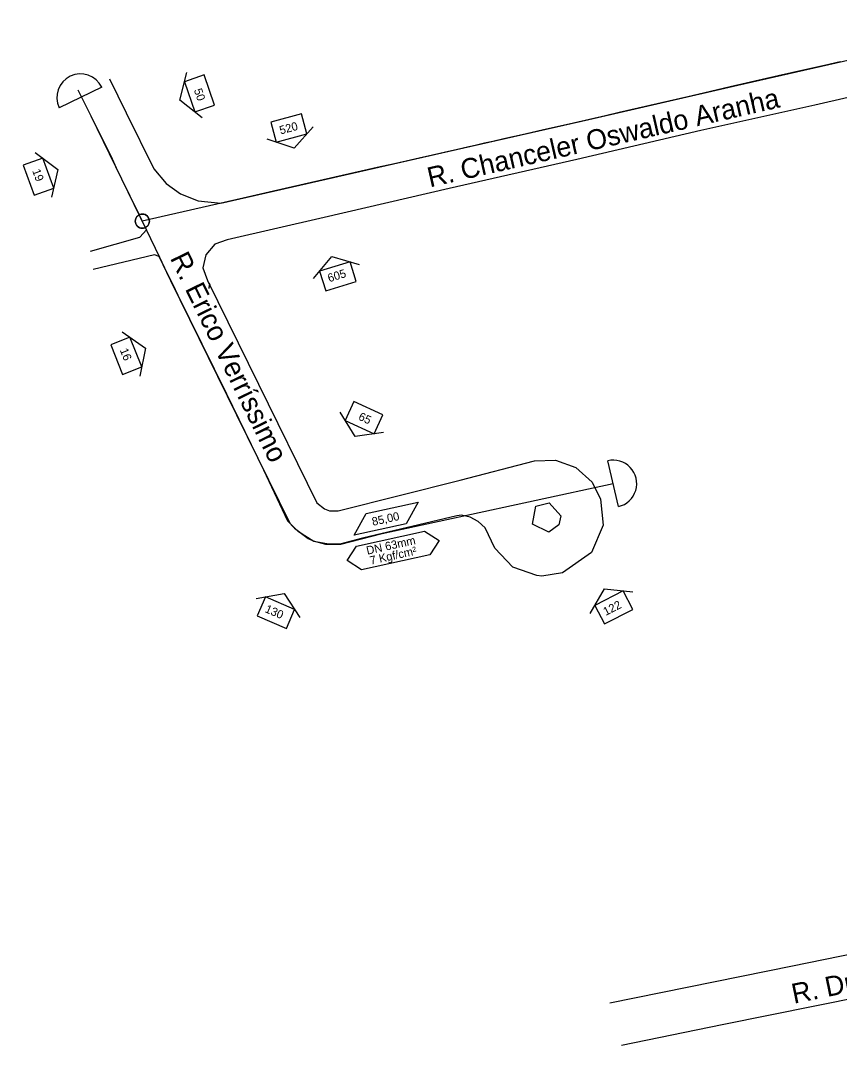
# Model space of a CAD drawing. Extents: x 656692 to 673945, y 7585994 to 7599066.
# Drawn here: x 669246.9 to 669542.8, y 7591875.8 to 7592245.9 of the extents above; entities that cross this region are included whole.
import ezdxf

# ---------------------------------------------------------------- set-up
doc = ezdxf.new("R2010")
doc.units = 0
for name, color, linetype in [('FORMATO', 7, 'Continuous'), ('LOGRADOURO', 7, 'Continuous'), ('LOGRADOURO_TEXTO', 7, 'Continuous'), ('NUM_REF', 7, 'Continuous'), ('SIMBOLO', 7, 'Continuous'), ('TEXTO', 7, 'Continuous'), ('TUBO_PEAD_GN_63', 7, 'Continuous')]:
    doc.layers.add(name, color=color, linetype=linetype)

# ---------------------------------------------------------------- blocks, each defined once
blk = doc.blocks.new('INTERLIGACAO_5')
at = {"layer": 'SIMBOLO'}
blk.add_circle((0, 0), 1.28, dxfattribs=at)
for start, end in [(0, 180), (180, 0)]:
    blk.add_arc((0, 0), 1.28, start, end, dxfattribs=at)
blk = doc.blocks.new('NUM_REF_1')
at = {"layer": 'NUM_REF'}
blk.add_lwpolyline([(-4.3125, 0.9375), (0, 3.75), (4.3125, 0.9375)], dxfattribs=at)
blk.add_lwpolyline([(2.875, -1.875), (2.875, 1.875), (-2.875, 1.875), (-2.875, -1.875)], close=True, dxfattribs=at)

msp = doc.modelspace()

# ---------------------------------------------------------------- linework, layer by layer
at = {"layer": 'LOGRADOURO'}
for p, q in [((669560.92, 7591895.46), (669500.38, 7591883.19)), ((669500.38, 7591883.19), (669464.04, 7591875.77))]:
    msp.add_line(p, q, dxfattribs=at)
for points in [[(669279.03, 7592224.82), (669285.08, 7592212.59), (669295.08, 7592192.38), (669299.57, 7592187.05), (669304.78, 7592183.35), (669311.1, 7592180.8), (669319.34, 7592179.89), (669366.91, 7592190.7), (669407.13, 7592199.85), (669452.22, 7592210.09), (669506.1, 7592222.54), (669608.86, 7592245.88)], [(669590.95, 7592228.47), (669533.91, 7592215.37), (669492.7, 7592206.11), (669447.87, 7592195.73), (669401.75, 7592185.24), (669356.58, 7592174.8), (669321.57, 7592166.64), (669317.14, 7592165.08), (669313.9, 7592161.3), (669312.82, 7592156.63), (669314.5, 7592152.04), (669332.94, 7592114.51), (669354.01, 7592071.73), (669356.7, 7592069.52), (669358.51, 7592068.81), (669361.71, 7592068.82), (669405.72, 7592079.95), (669432.59, 7592086.84), (669440.2, 7592087.14), (669447.49, 7592084.46), (669453.42, 7592079.17), (669456.44, 7592073.07), (669457.4, 7592063.66), (669453.21, 7592053.73), (669442.77, 7592046.45), (669435.2, 7592045.21), (669433.39, 7592045.48), (669424.75, 7592048.51), (669418.29, 7592055.4), (669414.77, 7592062.65), (669412.26, 7592065.01), (669409.39, 7592066.54), (669406.26, 7592067.31), (669404.59, 7592067.06), (669370.49, 7592058.99), (669362.33, 7592056.85), (669357.54, 7592056.87), (669352.93, 7592057.74), (669347.31, 7592061.29), (669344.38, 7592064.21), (669325.05, 7592103.39), (669301.28, 7592151.84), (669296.99, 7592160.69), (669295.29, 7592161.29), (669273.19, 7592155.92)], [(669272.22, 7592162.57), (669290.06, 7592167.69), (669292.45, 7592170.33), (669272.49, 7592211.29), (669267.82, 7592220.72)], [(669459.79, 7591891.13), (669525.83, 7591904.5), (669578.28, 7591915.3), (669653.98, 7591931.45), (669661.62, 7591932.86), (669663.09, 7591933.21), (669665.55, 7591934.7), (669695.76, 7591974.74), (669727.46, 7592017.52), (669754.41, 7592054.38), (669784.3, 7592095.47), (669786.61, 7592101.29), (669786.07, 7592105.33), (669782.71, 7592110.4), (669778.05, 7592113.09), (669776.37, 7592113.4), (669773.03, 7592113.16), (669768.83, 7592112.32), (669729.93, 7592104.37), (669688.75, 7592096.07), (669633.45, 7592085.1)], [(669431.83, 7592064), (669433.07, 7592070.53), (669437.93, 7592071.77), (669442.05, 7592067.08), (669441.38, 7592063.74), (669437.72, 7592061.14), (669431.83, 7592064)]]:
    msp.add_lwpolyline(points, dxfattribs=at)
at = {"layer": 'SIMBOLO'}
msp.add_lwpolyline([(669386.19, 7592064.12), (669367.42, 7592059.99), (669371.83, 7592067.87), (669390.6, 7592072)], close=True, dxfattribs=at)
msp.add_lwpolyline([(669364.93, 7592050.87), (669368.26, 7592056.08), (669392.92, 7592061.5), (669398.13, 7592058.17), (669394.8, 7592052.96), (669370.14, 7592047.54), (669364.93, 7592050.87)], dxfattribs=at)
at = {"layer": 'TUBO_PEAD_GN_63'}
for p, q in [((669276.27, 7592221.76), (669260.93, 7592214.4)), ((669462.97, 7592070.37), (669459.03, 7592086.92))]:
    msp.add_line(p, q, dxfattribs=at)
for points in [[(669543.01, 7592230.98), (669537.32, 7592229.65), (669529.17, 7592227.79), (669520.59, 7592225.86), (669510.6, 7592223.59), (669503.28, 7592221.89), (669496.22, 7592220.29), (669487.93, 7592218.35), (669463.18, 7592212.64), (669458.29, 7592211.5), (669452.45, 7592210.16), (669446.66, 7592208.86), (669440.82, 7592207.5), (669435.86, 7592206.39), (669429.76, 7592204.98), (669425.39, 7592204.02), (669421.5, 7592203.13), (669417.54, 7592202.24), (669414.51, 7592201.53), (669411.14, 7592200.79), (669408.9, 7592200.26), (669404.8, 7592199.32), (669400, 7592198.24), (669395.74, 7592197.28), (669390.9, 7592196.16), (669386.19, 7592195.09), (669380.89, 7592193.89), (669376.82, 7592192.99), (669338.35, 7592184.23), (669327.31, 7592181.7), (669290.94, 7592173.42)], [(669269.07, 7592217.96), (669276.42, 7592203.22), (669279.99, 7592195.99), (669282.03, 7592191.63), (669283.92, 7592187.79), (669286.48, 7592182.55), (669288.71, 7592177.98), (669290.69, 7592173.95), (669292.44, 7592170.34)], [(669292.37, 7592170.36), (669297.13, 7592160.37), (669299.85, 7592154.79), (669300.75, 7592152.93), (669301.93, 7592150.53), (669302.77, 7592148.79), (669303.8, 7592146.68), (669304.53, 7592145.25), (669306.55, 7592141.12), (669308, 7592138.17), (669321.29, 7592111.08), (669334.73, 7592083.64), (669343.32, 7592065.25), (669345.96, 7592062.53), (669350.85, 7592058.9), (669352.65, 7592058.03), (669357.07, 7592056.82), (669362.62, 7592056.82), (669377.57, 7592060.59), (669461.02, 7592078.69)]]:
    msp.add_lwpolyline(points, dxfattribs=at)
for centre, start, end in [((669268.6, 7592218.08), 25.6252, 205.6252), ((669461, 7592078.65), 283.3649, 103.3649)]:
    msp.add_arc(centre, 8.51, start, end, dxfattribs=at)

# ---------------------------------------------------------------- block references
at = {"layer": 'FORMATO'}
for p, xscale, yscale, rotation in [((669311.56, 7592219.55), 2.0000000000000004, 1.9999999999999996, 108.979110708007), ((669343.89, 7592207.08), 2, 2, -164.99935316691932), ((669253.43, 7592189.49), 1.9999999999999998, 1.9999999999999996, -69.84205923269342), ((669361.57, 7592153.49), 2.0000000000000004, 2, 17.10672016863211), ((669285.14, 7592124.79), 2, 2, -68.098169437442), ((669371.02, 7592102.49), 1.9999999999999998, 1.9999999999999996, 155.17997588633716), ((669339.19, 7592032.06), 2, 2, -23.280683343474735), ((669461.24, 7592033.96), 2, 2, 27.021044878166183)]:
    msp.add_blockref('NUM_REF_1', p, dxfattribs=dict(at, xscale=xscale, yscale=yscale, rotation=rotation))
at = {"layer": 'SIMBOLO', "xscale": 2, "yscale": 2, "rotation": 55.661417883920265}
msp.add_blockref('INTERLIGACAO_5', (669290.94, 7592173.42), dxfattribs=at)

# ---------------------------------------------------------------- texts
for s, rotation, p in [('50', 288.9791, (669309.52, 7592220.77)), ('520', 15.0006, (669340.91, 7592204.72)), ('19', 290.1579, (669251.12, 7592191.65)), ('605', 17.1067, (669358.43, 7592151.35)), ('16', 291.9018, (669282.77, 7592126.87)), ('65', 335.18, (669368.73, 7592101.85)), ('130', 336.7193, (669334.97, 7592032.33)), ('122', 27.021, (669458.34, 7592030.88))]:
    msp.add_text(s, height=3, rotation=rotation).set_placement(p)
at = {"layer": 'LOGRADOURO_TEXTO'}
for s, rotation, p in [('R. Chanceler Oswaldo Aranha ', 12.884, (669394.81, 7592185.59)), ('R. Èrico Verríssimo', 296.0423, (669300.82, 7592160.1)), ('R. Dr. Romualdo', 11.5121, (669526.27, 7591890.83))]:
    msp.add_text(s, height=7.2, rotation=rotation, dxfattribs=at).set_placement(p)
at = {"layer": 'TEXTO'}
for s, p in [('85,00', (669374.21, 7592063.41)), ('DN 63mm', (669372.21, 7592052.98)), ('7 Kgf/cm²', (669373.48, 7592049.37))]:
    msp.add_text(s, height=3, rotation=12.3989, dxfattribs=at).set_placement(p)

doc.saveas('drawing.dxf')
